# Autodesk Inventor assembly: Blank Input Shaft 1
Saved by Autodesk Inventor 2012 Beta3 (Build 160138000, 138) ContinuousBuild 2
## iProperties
Created: 2011-01
Part Number: Blank Input Shaft 1
Document SubType Name: Assembly
Designer: Beta-8540w
ClientObjectVersion: 1
Author: Beta-8540w
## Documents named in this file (2)
- C:\Inventor 2012 Essentials\Assemblies\Chapter 8\Design Accelerators\Blank Input Shaft 1.iam
- C:\Inventor 2012 Essentials\Assemblies\Chapter 8\Design Accelerators\Blank Input Shaft 1.ipt
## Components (1 placed, 1 different names)
1. Blank Input Shaft 1:1
